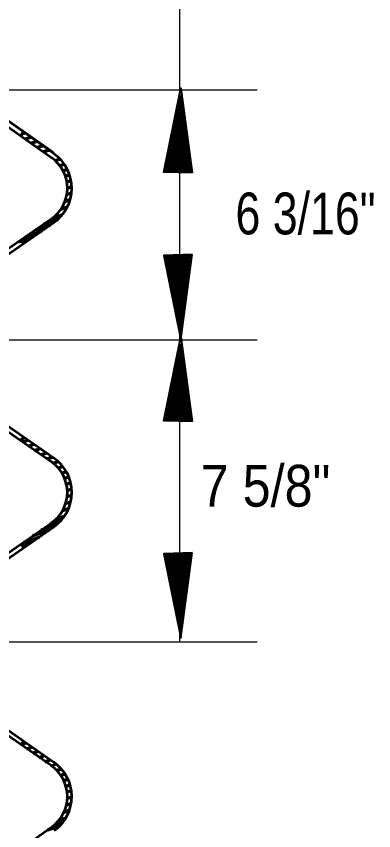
# Model space of a CAD drawing. Extents: x 856.9 to 891.7, y -2278.5 to -2254.7.
# Drawn here: x 865.843 to 866.943, y -2260.699 to -2258.193 of the extents above; entities that cross this region are included whole.
import ezdxf

# ---------------------------------------------------------------- set-up
doc = ezdxf.new("R2010")
doc.units = 0
doc.header["$LTSCALE"] = 0.051
doc.layers.add('1', color=7, linetype='Continuous', lineweight=70)
doc.layers.add('3', color=7, linetype='Continuous', lineweight=40)

msp = doc.modelspace()

# ---------------------------------------------------------------- hatches: boundary and pattern name
at = {"layer": '3'}
for points in [[(866.38433, -2258.675), (866.29767, -2258.67208), (866.34983, -2258.41367), (866.34983, -2258.41367)], [(866.38, -2258.67375), (866.302, -2258.671), (866.349, -2258.43842), (866.349, -2258.43842)], [(866.37608, -2258.6725), (866.306, -2258.67017), (866.34825, -2258.46083), (866.34825, -2258.46083)], [(866.37267, -2258.6715), (866.30958, -2258.66933), (866.34758, -2258.48083), (866.34758, -2258.48083)], [(866.36967, -2258.67058), (866.31283, -2258.66867), (866.347, -2258.49892), (866.347, -2258.49892)], [(866.36675, -2258.6695), (866.31567, -2258.66792), (866.3465, -2258.51517), (866.3465, -2258.51517)], [(866.36417, -2258.66883), (866.31825, -2258.66733), (866.346, -2258.52992), (866.346, -2258.52992)], [(866.362, -2258.668), (866.3205, -2258.66675), (866.3455, -2258.54317), (866.3455, -2258.54317)], [(866.36, -2258.66758), (866.32258, -2258.66625), (866.345, -2258.55492), (866.345, -2258.55492)], [(866.358, -2258.66683), (866.32433, -2258.66567), (866.34467, -2258.56575), (866.34467, -2258.56575)], [(866.3565, -2258.66642), (866.32617, -2258.66533), (866.34442, -2258.57533), (866.34442, -2258.57533)], [(866.35492, -2258.66592), (866.32775, -2258.66492), (866.344, -2258.58392), (866.344, -2258.58392)], [(866.35358, -2258.6655), (866.32908, -2258.66467), (866.34375, -2258.59183), (866.34375, -2258.59183)], [(866.35233, -2258.66492), (866.33025, -2258.66442), (866.34358, -2258.59875), (866.34358, -2258.59875)], [(866.35125, -2258.66475), (866.33142, -2258.66408), (866.34342, -2258.605), (866.34342, -2258.605)], [(866.35025, -2258.66433), (866.33242, -2258.66392), (866.34308, -2258.61067), (866.34308, -2258.61067)], [(866.34933, -2258.66417), (866.33325, -2258.66358), (866.34292, -2258.61575), (866.34292, -2258.61575)], [(866.3485, -2258.664), (866.33408, -2258.66342), (866.34275, -2258.62033), (866.34275, -2258.62033)], [(866.34808, -2258.66358), (866.33492, -2258.66333), (866.34275, -2258.62442), (866.34275, -2258.62442)], [(866.3475, -2258.66342), (866.33567, -2258.663), (866.34267, -2258.62808), (866.34267, -2258.62808)], [(866.347, -2258.66308), (866.33642, -2258.66267), (866.34283, -2258.63133), (866.34283, -2258.63133)], [(866.34642, -2258.66308), (866.337, -2258.66267), (866.34267, -2258.63442), (866.34267, -2258.63442)], [(866.34592, -2258.66292), (866.33742, -2258.66258), (866.34242, -2258.63717), (866.34242, -2258.63717)], [(866.3455, -2258.66267), (866.33792, -2258.6625), (866.3425, -2258.6395), (866.3425, -2258.6395)], [(866.38433, -2258.92583), (866.29767, -2258.92875), (866.34983, -2259.18717), (866.34983, -2259.18717)], [(866.38, -2258.92708), (866.302, -2258.92983), (866.349, -2259.16242), (866.349, -2259.16242)], [(866.37608, -2258.92833), (866.306, -2258.93067), (866.34825, -2259.14), (866.34825, -2259.14)], [(866.37267, -2258.92933), (866.30958, -2258.9315), (866.34758, -2259.12), (866.34758, -2259.12)], [(866.36967, -2258.93025), (866.31283, -2258.93217), (866.347, -2259.10192), (866.347, -2259.10192)], [(866.36675, -2258.93133), (866.31567, -2258.93292), (866.3465, -2259.08567), (866.3465, -2259.08567)], [(866.36417, -2258.932), (866.31825, -2258.9335), (866.346, -2259.07092), (866.346, -2259.07092)], [(866.362, -2258.93283), (866.3205, -2258.93408), (866.3455, -2259.05767), (866.3455, -2259.05767)], [(866.36, -2258.93325), (866.32258, -2258.93458), (866.345, -2259.04592), (866.345, -2259.04592)], [(866.358, -2258.934), (866.32433, -2258.93517), (866.34467, -2259.03508), (866.34467, -2259.03508)], [(866.3565, -2258.93442), (866.32617, -2258.9355), (866.34442, -2259.0255), (866.34442, -2259.0255)], [(866.35492, -2258.93492), (866.32775, -2258.93592), (866.344, -2259.01692), (866.344, -2259.01692)], [(866.35358, -2258.93533), (866.32908, -2258.93617), (866.34375, -2259.009), (866.34375, -2259.009)], [(866.35233, -2258.93592), (866.33025, -2258.93642), (866.34358, -2259.00208), (866.34358, -2259.00208)], [(866.35125, -2258.93608), (866.33142, -2258.93675), (866.34342, -2258.99583), (866.34342, -2258.99583)], [(866.35025, -2258.9365), (866.33242, -2258.93692), (866.34308, -2258.99017), (866.34308, -2258.99017)], [(866.34933, -2258.93667), (866.33325, -2258.93725), (866.34292, -2258.98508), (866.34292, -2258.98508)], [(866.3485, -2258.93683), (866.33408, -2258.93742), (866.34275, -2258.9805), (866.34275, -2258.9805)], [(866.34808, -2258.93725), (866.33492, -2258.9375), (866.34275, -2258.97642), (866.34275, -2258.97642)], [(866.3475, -2258.93742), (866.33567, -2258.93783), (866.34267, -2258.97275), (866.34267, -2258.97275)], [(866.347, -2258.93775), (866.33642, -2258.93817), (866.34283, -2258.9695), (866.34283, -2258.9695)], [(866.34642, -2258.93775), (866.337, -2258.93817), (866.34267, -2258.96642), (866.34267, -2258.96642)], [(866.34592, -2258.93792), (866.33742, -2258.93825), (866.34242, -2258.96367), (866.34242, -2258.96367)], [(866.3455, -2258.93817), (866.33792, -2258.93833), (866.3425, -2258.96133), (866.3425, -2258.96133)], [(866.38433, -2259.44017), (866.29767, -2259.43725), (866.34983, -2259.17883), (866.34983, -2259.17883)], [(866.38, -2259.43892), (866.302, -2259.43617), (866.349, -2259.20358), (866.349, -2259.20358)], [(866.37608, -2259.43767), (866.306, -2259.43533), (866.34825, -2259.226), (866.34825, -2259.226)], [(866.37267, -2259.43667), (866.30958, -2259.4345), (866.34758, -2259.246), (866.34758, -2259.246)], [(866.36967, -2259.43575), (866.31283, -2259.43383), (866.347, -2259.26408), (866.347, -2259.26408)], [(866.36675, -2259.43467), (866.31567, -2259.43308), (866.3465, -2259.28033), (866.3465, -2259.28033)], [(866.36417, -2259.434), (866.31825, -2259.4325), (866.346, -2259.29508), (866.346, -2259.29508)], [(866.362, -2259.43317), (866.3205, -2259.43192), (866.3455, -2259.30833), (866.3455, -2259.30833)], [(866.36, -2259.43275), (866.32258, -2259.43142), (866.345, -2259.32008), (866.345, -2259.32008)], [(866.358, -2259.432), (866.32433, -2259.43083), (866.34467, -2259.33092), (866.34467, -2259.33092)], [(866.3565, -2259.43158), (866.32617, -2259.4305), (866.34442, -2259.3405), (866.34442, -2259.3405)], [(866.35492, -2259.43108), (866.32775, -2259.43008), (866.344, -2259.34908), (866.344, -2259.34908)], [(866.35358, -2259.43067), (866.32908, -2259.42983), (866.34375, -2259.357), (866.34375, -2259.357)], [(866.35233, -2259.43008), (866.33025, -2259.42958), (866.34358, -2259.36392), (866.34358, -2259.36392)], [(866.35125, -2259.42992), (866.33142, -2259.42925), (866.34342, -2259.37017), (866.34342, -2259.37017)], [(866.35025, -2259.4295), (866.33242, -2259.42908), (866.34308, -2259.37583), (866.34308, -2259.37583)], [(866.34933, -2259.42933), (866.33325, -2259.42875), (866.34292, -2259.38092), (866.34292, -2259.38092)], [(866.3485, -2259.42917), (866.33408, -2259.42858), (866.34275, -2259.3855), (866.34275, -2259.3855)], [(866.34808, -2259.42875), (866.33492, -2259.4285), (866.34275, -2259.38958), (866.34275, -2259.38958)], [(866.3475, -2259.42858), (866.33567, -2259.42817), (866.34267, -2259.39325), (866.34267, -2259.39325)], [(866.347, -2259.42825), (866.33642, -2259.42783), (866.34283, -2259.3965), (866.34283, -2259.3965)], [(866.34642, -2259.42825), (866.337, -2259.42783), (866.34267, -2259.39958), (866.34267, -2259.39958)], [(866.34592, -2259.42808), (866.33742, -2259.42775), (866.34242, -2259.40233), (866.34242, -2259.40233)], [(866.3455, -2259.42783), (866.33792, -2259.42767), (866.3425, -2259.40467), (866.3425, -2259.40467)], [(866.38433, -2259.84417), (866.29767, -2259.84708), (866.34983, -2260.1055), (866.34983, -2260.1055)], [(866.38, -2259.84542), (866.302, -2259.84817), (866.349, -2260.08075), (866.349, -2260.08075)], [(866.37608, -2259.84667), (866.306, -2259.849), (866.34825, -2260.05833), (866.34825, -2260.05833)], [(866.37267, -2259.84767), (866.30958, -2259.84983), (866.34758, -2260.03833), (866.34758, -2260.03833)], [(866.36967, -2259.84858), (866.31283, -2259.8505), (866.347, -2260.02025), (866.347, -2260.02025)], [(866.36675, -2259.84967), (866.31567, -2259.85125), (866.3465, -2260.004), (866.3465, -2260.004)], [(866.36417, -2259.85033), (866.31825, -2259.85183), (866.346, -2259.98925), (866.346, -2259.98925)], [(866.362, -2259.85117), (866.3205, -2259.85242), (866.3455, -2259.976), (866.3455, -2259.976)], [(866.36, -2259.85158), (866.32258, -2259.85292), (866.345, -2259.96425), (866.345, -2259.96425)], [(866.358, -2259.85233), (866.32433, -2259.8535), (866.34467, -2259.95342), (866.34467, -2259.95342)], [(866.3565, -2259.85275), (866.32617, -2259.85383), (866.34442, -2259.94383), (866.34442, -2259.94383)], [(866.35492, -2259.85325), (866.32775, -2259.85425), (866.344, -2259.93525), (866.344, -2259.93525)], [(866.35358, -2259.85367), (866.32908, -2259.8545), (866.34375, -2259.92733), (866.34375, -2259.92733)], [(866.35233, -2259.85425), (866.33025, -2259.85475), (866.34358, -2259.92042), (866.34358, -2259.92042)], [(866.35125, -2259.85442), (866.33142, -2259.85508), (866.34342, -2259.91417), (866.34342, -2259.91417)], [(866.35025, -2259.85483), (866.33242, -2259.85525), (866.34308, -2259.9085), (866.34308, -2259.9085)], [(866.34933, -2259.855), (866.33325, -2259.85558), (866.34292, -2259.90342), (866.34292, -2259.90342)], [(866.3485, -2259.85517), (866.33408, -2259.85575), (866.34275, -2259.89883), (866.34275, -2259.89883)], [(866.34808, -2259.85558), (866.33492, -2259.85583), (866.34275, -2259.89475), (866.34275, -2259.89475)], [(866.3475, -2259.85575), (866.33567, -2259.85617), (866.34267, -2259.89108), (866.34267, -2259.89108)], [(866.347, -2259.85608), (866.33642, -2259.8565), (866.34283, -2259.88783), (866.34283, -2259.88783)], [(866.34642, -2259.85608), (866.337, -2259.8565), (866.34267, -2259.88475), (866.34267, -2259.88475)], [(866.34592, -2259.85625), (866.33742, -2259.85658), (866.34242, -2259.882), (866.34242, -2259.882)], [(866.3455, -2259.8565), (866.33792, -2259.85667), (866.3425, -2259.87967), (866.3425, -2259.87967)]]:
    msp.add_hatch(color=256, dxfattribs=at).paths.add_polyline_path(points)

# ---------------------------------------------------------------- linework, layer by layer
at = {"layer": '1', "lineweight": 25}
for p, q in [((866.347, -2260.11883), (866.347, -2257.74608)), ((866.58492, -2258.42008), (865.81925, -2258.42008)), ((866.58492, -2259.18958), (863.90775, -2259.18958)), ((866.58492, -2260.11883), (863.90775, -2260.11883))]:
    msp.add_line(p, q, dxfattribs=at)
at = {"layer": '1', "lineweight": 53}
for p, q in [((865.73217, -2258.47225), (865.95233, -2258.62867)), ((865.96092, -2258.61692), (865.74108, -2258.4605)), ((865.95633, -2258.61175), (865.74108, -2258.46092)), ((865.95067, -2258.81675), (865.66458, -2259.01475)), ((865.67217, -2259.0265), (865.95933, -2258.82742)), ((865.95933, -2259.5525), (865.67217, -2259.35342)), ((865.66458, -2259.3655), (865.95067, -2259.56317)), ((865.95067, -2259.75317), (865.66458, -2259.95042)), ((865.67217, -2259.96175), (865.95933, -2259.76342)), ((865.95067, -2260.49867), (865.66458, -2260.30117)), ((865.95933, -2260.48867), (865.67217, -2260.28917)), ((865.95067, -2260.49867), (865.96717, -2260.49417)), ((865.95233, -2260.68767), (865.73258, -2260.844))]:
    msp.add_line(p, q, dxfattribs=at)
at = {"layer": '1'}
for p, q in [((865.85767, -2258.56075), (865.86492, -2258.5505)), ((865.86367, -2258.5535), (865.86792, -2258.55217)), ((865.87092, -2258.56967), (865.88708, -2258.56525)), ((865.88858, -2258.58317), (865.90458, -2258.57842)), ((865.90792, -2258.596), (865.92417, -2258.59192)), ((865.92708, -2258.60917), (865.94317, -2258.60492)), ((865.96233, -2258.63725), (865.97708, -2258.6315)), ((865.97708, -2258.65192), (865.99017, -2258.64775)), ((865.98758, -2258.668), (866.00058, -2258.66375)), ((865.99467, -2258.6845), (866.00808, -2258.68)), ((865.99917, -2258.70217), (866.01258, -2258.69792)), ((866.00058, -2258.7215), (866.01383, -2258.71717)), ((865.99317, -2258.76275), (866.00933, -2258.75675)), ((865.99917, -2258.74067), (866.01383, -2258.73617)), ((865.98158, -2258.786), (866.00058, -2258.779)), ((865.95483, -2258.81425), (865.98442, -2258.804)), ((865.90342, -2258.84975), (865.94742, -2258.83517)), ((865.92858, -2258.83175), (865.97108, -2258.818)), ((865.87692, -2258.86892), (865.92108, -2258.854)), ((865.85033, -2258.8865), (865.89458, -2258.87167)), ((865.85767, -2258.88067), (865.86642, -2258.89225)), ((865.85767, -2259.49967), (865.86642, -2259.48767)), ((865.86217, -2259.50242), (865.87842, -2259.49667)), ((865.88133, -2259.51575), (865.89758, -2259.50975)), ((865.90017, -2259.529), (865.91658, -2259.52292)), ((865.91967, -2259.54092), (865.93608, -2259.53642)), ((865.93883, -2259.55375), (865.95492, -2259.5495)), ((865.95792, -2259.5675), (865.97258, -2259.56317)), ((865.97258, -2259.58217), (865.98592, -2259.57775)), ((865.98442, -2259.59825), (865.99767, -2259.59392)), ((865.99192, -2259.6145), (866.00508, -2259.61)), ((865.99767, -2259.63217), (866.01108, -2259.6275)), ((866.00058, -2259.6515), (866.01383, -2259.64717)), ((865.99642, -2259.691), (866.01108, -2259.6865)), ((865.99917, -2259.67042), (866.01383, -2259.66592)), ((865.98592, -2259.71342), (866.00358, -2259.70717)), ((865.96717, -2259.73942), (865.99192, -2259.731)), ((865.92108, -2259.7735), (865.96533, -2259.75892)), ((865.94742, -2259.75592), (865.98158, -2259.74417)), ((865.89458, -2259.791), (865.94058, -2259.77642)), ((865.86792, -2259.81067), (865.91392, -2259.79592)), ((865.85767, -2259.81625), (865.86642, -2259.82775)), ((865.86217, -2259.82217), (865.88708, -2259.81317)), ((865.85767, -2260.43525), (865.86642, -2260.42342)), ((865.86067, -2260.43225), (865.87242, -2260.42792)), ((865.87508, -2260.44692), (865.89142, -2260.44142)), ((865.89458, -2260.46042), (865.91067, -2260.45417)), ((865.91392, -2260.47367), (865.93008, -2260.4675)), ((865.93133, -2260.487), (865.94742, -2260.48075)), ((865.96833, -2260.513), (865.98158, -2260.50925)), ((865.97992, -2260.528), (865.99317, -2260.52375)), ((865.99017, -2260.54442), (866.00208, -2260.53967)), ((865.99642, -2260.562), (866.00933, -2260.5575)), ((865.99917, -2260.57967), (866.01258, -2260.57525)), ((866.00058, -2260.59892), (866.01383, -2260.59442)), ((865.99017, -2260.64167), (866.00658, -2260.63567)), ((865.99767, -2260.6195), (866.01258, -2260.615)), ((865.97542, -2260.66517), (865.99642, -2260.65925)), ((865.94058, -2260.696), (865.97708, -2260.68425)), ((865.96233, -2260.67992), (865.98867, -2260.67117))]:
    msp.add_line(p, q, dxfattribs=at)
at = {"layer": '1', "lineweight": 53}
for centre, radius, start, end in [((865.88544, -2258.72184), 0.11508, 304.74043, 54.50779), ((865.88544, -2258.72184), 0.12871, 304.74043, 54.5106), ((865.88544, -2259.65784), 0.12871, 304.74043, 55.25957), ((865.88544, -2259.65784), 0.11508, 304.73767, 55.26233), ((865.88544, -2260.59384), 0.12871, 305.4894, 55.25957), ((865.88544, -2260.59384), 0.11508, 305.49221, 55.25957)]:
    msp.add_arc(centre, radius, start, end, dxfattribs=at)
at = {"layer": '3'}
for points in [[(866.38433, -2258.675), (866.29767, -2258.67208), (866.34983, -2258.41367), (866.34983, -2258.41367)], [(866.38, -2258.67375), (866.302, -2258.671), (866.349, -2258.43842), (866.349, -2258.43842)], [(866.37608, -2258.6725), (866.306, -2258.67017), (866.34825, -2258.46083), (866.34825, -2258.46083)], [(866.37267, -2258.6715), (866.30958, -2258.66933), (866.34758, -2258.48083), (866.34758, -2258.48083)], [(866.36967, -2258.67058), (866.31283, -2258.66867), (866.347, -2258.49892), (866.347, -2258.49892)], [(866.36675, -2258.6695), (866.31567, -2258.66792), (866.3465, -2258.51517), (866.3465, -2258.51517)], [(866.36417, -2258.66883), (866.31825, -2258.66733), (866.346, -2258.52992), (866.346, -2258.52992)], [(866.362, -2258.668), (866.3205, -2258.66675), (866.3455, -2258.54317), (866.3455, -2258.54317)], [(866.36, -2258.66758), (866.32258, -2258.66625), (866.345, -2258.55492), (866.345, -2258.55492)], [(866.358, -2258.66683), (866.32433, -2258.66567), (866.34467, -2258.56575), (866.34467, -2258.56575)], [(866.3565, -2258.66642), (866.32617, -2258.66533), (866.34442, -2258.57533), (866.34442, -2258.57533)], [(866.35492, -2258.66592), (866.32775, -2258.66492), (866.344, -2258.58392), (866.344, -2258.58392)], [(866.35358, -2258.6655), (866.32908, -2258.66467), (866.34375, -2258.59183), (866.34375, -2258.59183)], [(866.35233, -2258.66492), (866.33025, -2258.66442), (866.34358, -2258.59875), (866.34358, -2258.59875)], [(866.35125, -2258.66475), (866.33142, -2258.66408), (866.34342, -2258.605), (866.34342, -2258.605)], [(866.35025, -2258.66433), (866.33242, -2258.66392), (866.34308, -2258.61067), (866.34308, -2258.61067)], [(866.34933, -2258.66417), (866.33325, -2258.66358), (866.34292, -2258.61575), (866.34292, -2258.61575)], [(866.3485, -2258.664), (866.33408, -2258.66342), (866.34275, -2258.62033), (866.34275, -2258.62033)], [(866.34808, -2258.66358), (866.33492, -2258.66333), (866.34275, -2258.62442), (866.34275, -2258.62442)], [(866.3475, -2258.66342), (866.33567, -2258.663), (866.34267, -2258.62808), (866.34267, -2258.62808)], [(866.347, -2258.66308), (866.33642, -2258.66267), (866.34283, -2258.63133), (866.34283, -2258.63133)], [(866.34642, -2258.66308), (866.337, -2258.66267), (866.34267, -2258.63442), (866.34267, -2258.63442)], [(866.34592, -2258.66292), (866.33742, -2258.66258), (866.34242, -2258.63717), (866.34242, -2258.63717)], [(866.3455, -2258.66267), (866.33792, -2258.6625), (866.3425, -2258.6395), (866.3425, -2258.6395)], [(866.38433, -2258.92583), (866.29767, -2258.92875), (866.34983, -2259.18717), (866.34983, -2259.18717)], [(866.38, -2258.92708), (866.302, -2258.92983), (866.349, -2259.16242), (866.349, -2259.16242)], [(866.37608, -2258.92833), (866.306, -2258.93067), (866.34825, -2259.14), (866.34825, -2259.14)], [(866.37267, -2258.92933), (866.30958, -2258.9315), (866.34758, -2259.12), (866.34758, -2259.12)], [(866.36967, -2258.93025), (866.31283, -2258.93217), (866.347, -2259.10192), (866.347, -2259.10192)], [(866.36675, -2258.93133), (866.31567, -2258.93292), (866.3465, -2259.08567), (866.3465, -2259.08567)], [(866.36417, -2258.932), (866.31825, -2258.9335), (866.346, -2259.07092), (866.346, -2259.07092)], [(866.362, -2258.93283), (866.3205, -2258.93408), (866.3455, -2259.05767), (866.3455, -2259.05767)], [(866.36, -2258.93325), (866.32258, -2258.93458), (866.345, -2259.04592), (866.345, -2259.04592)], [(866.358, -2258.934), (866.32433, -2258.93517), (866.34467, -2259.03508), (866.34467, -2259.03508)], [(866.3565, -2258.93442), (866.32617, -2258.9355), (866.34442, -2259.0255), (866.34442, -2259.0255)], [(866.35492, -2258.93492), (866.32775, -2258.93592), (866.344, -2259.01692), (866.344, -2259.01692)], [(866.35358, -2258.93533), (866.32908, -2258.93617), (866.34375, -2259.009), (866.34375, -2259.009)], [(866.35233, -2258.93592), (866.33025, -2258.93642), (866.34358, -2259.00208), (866.34358, -2259.00208)], [(866.35125, -2258.93608), (866.33142, -2258.93675), (866.34342, -2258.99583), (866.34342, -2258.99583)], [(866.35025, -2258.9365), (866.33242, -2258.93692), (866.34308, -2258.99017), (866.34308, -2258.99017)], [(866.34933, -2258.93667), (866.33325, -2258.93725), (866.34292, -2258.98508), (866.34292, -2258.98508)], [(866.3485, -2258.93683), (866.33408, -2258.93742), (866.34275, -2258.9805), (866.34275, -2258.9805)], [(866.34808, -2258.93725), (866.33492, -2258.9375), (866.34275, -2258.97642), (866.34275, -2258.97642)], [(866.3475, -2258.93742), (866.33567, -2258.93783), (866.34267, -2258.97275), (866.34267, -2258.97275)], [(866.347, -2258.93775), (866.33642, -2258.93817), (866.34283, -2258.9695), (866.34283, -2258.9695)], [(866.34642, -2258.93775), (866.337, -2258.93817), (866.34267, -2258.96642), (866.34267, -2258.96642)], [(866.34592, -2258.93792), (866.33742, -2258.93825), (866.34242, -2258.96367), (866.34242, -2258.96367)], [(866.3455, -2258.93817), (866.33792, -2258.93833), (866.3425, -2258.96133), (866.3425, -2258.96133)], [(866.38433, -2259.44017), (866.29767, -2259.43725), (866.34983, -2259.17883), (866.34983, -2259.17883)], [(866.38, -2259.43892), (866.302, -2259.43617), (866.349, -2259.20358), (866.349, -2259.20358)], [(866.37608, -2259.43767), (866.306, -2259.43533), (866.34825, -2259.226), (866.34825, -2259.226)], [(866.37267, -2259.43667), (866.30958, -2259.4345), (866.34758, -2259.246), (866.34758, -2259.246)], [(866.36967, -2259.43575), (866.31283, -2259.43383), (866.347, -2259.26408), (866.347, -2259.26408)], [(866.36675, -2259.43467), (866.31567, -2259.43308), (866.3465, -2259.28033), (866.3465, -2259.28033)], [(866.36417, -2259.434), (866.31825, -2259.4325), (866.346, -2259.29508), (866.346, -2259.29508)], [(866.362, -2259.43317), (866.3205, -2259.43192), (866.3455, -2259.30833), (866.3455, -2259.30833)], [(866.36, -2259.43275), (866.32258, -2259.43142), (866.345, -2259.32008), (866.345, -2259.32008)], [(866.358, -2259.432), (866.32433, -2259.43083), (866.34467, -2259.33092), (866.34467, -2259.33092)], [(866.3565, -2259.43158), (866.32617, -2259.4305), (866.34442, -2259.3405), (866.34442, -2259.3405)], [(866.35492, -2259.43108), (866.32775, -2259.43008), (866.344, -2259.34908), (866.344, -2259.34908)], [(866.35358, -2259.43067), (866.32908, -2259.42983), (866.34375, -2259.357), (866.34375, -2259.357)], [(866.35233, -2259.43008), (866.33025, -2259.42958), (866.34358, -2259.36392), (866.34358, -2259.36392)], [(866.35125, -2259.42992), (866.33142, -2259.42925), (866.34342, -2259.37017), (866.34342, -2259.37017)], [(866.35025, -2259.4295), (866.33242, -2259.42908), (866.34308, -2259.37583), (866.34308, -2259.37583)], [(866.34933, -2259.42933), (866.33325, -2259.42875), (866.34292, -2259.38092), (866.34292, -2259.38092)], [(866.3485, -2259.42917), (866.33408, -2259.42858), (866.34275, -2259.3855), (866.34275, -2259.3855)], [(866.34808, -2259.42875), (866.33492, -2259.4285), (866.34275, -2259.38958), (866.34275, -2259.38958)], [(866.3475, -2259.42858), (866.33567, -2259.42817), (866.34267, -2259.39325), (866.34267, -2259.39325)], [(866.347, -2259.42825), (866.33642, -2259.42783), (866.34283, -2259.3965), (866.34283, -2259.3965)], [(866.34642, -2259.42825), (866.337, -2259.42783), (866.34267, -2259.39958), (866.34267, -2259.39958)], [(866.34592, -2259.42808), (866.33742, -2259.42775), (866.34242, -2259.40233), (866.34242, -2259.40233)], [(866.3455, -2259.42783), (866.33792, -2259.42767), (866.3425, -2259.40467), (866.3425, -2259.40467)], [(866.38433, -2259.84417), (866.29767, -2259.84708), (866.34983, -2260.1055), (866.34983, -2260.1055)], [(866.38, -2259.84542), (866.302, -2259.84817), (866.349, -2260.08075), (866.349, -2260.08075)], [(866.37608, -2259.84667), (866.306, -2259.849), (866.34825, -2260.05833), (866.34825, -2260.05833)], [(866.37267, -2259.84767), (866.30958, -2259.84983), (866.34758, -2260.03833), (866.34758, -2260.03833)], [(866.36967, -2259.84858), (866.31283, -2259.8505), (866.347, -2260.02025), (866.347, -2260.02025)], [(866.36675, -2259.84967), (866.31567, -2259.85125), (866.3465, -2260.004), (866.3465, -2260.004)], [(866.36417, -2259.85033), (866.31825, -2259.85183), (866.346, -2259.98925), (866.346, -2259.98925)], [(866.362, -2259.85117), (866.3205, -2259.85242), (866.3455, -2259.976), (866.3455, -2259.976)], [(866.36, -2259.85158), (866.32258, -2259.85292), (866.345, -2259.96425), (866.345, -2259.96425)], [(866.358, -2259.85233), (866.32433, -2259.8535), (866.34467, -2259.95342), (866.34467, -2259.95342)], [(866.3565, -2259.85275), (866.32617, -2259.85383), (866.34442, -2259.94383), (866.34442, -2259.94383)], [(866.35492, -2259.85325), (866.32775, -2259.85425), (866.344, -2259.93525), (866.344, -2259.93525)], [(866.35358, -2259.85367), (866.32908, -2259.8545), (866.34375, -2259.92733), (866.34375, -2259.92733)], [(866.35233, -2259.85425), (866.33025, -2259.85475), (866.34358, -2259.92042), (866.34358, -2259.92042)], [(866.35125, -2259.85442), (866.33142, -2259.85508), (866.34342, -2259.91417), (866.34342, -2259.91417)], [(866.35025, -2259.85483), (866.33242, -2259.85525), (866.34308, -2259.9085), (866.34308, -2259.9085)], [(866.34933, -2259.855), (866.33325, -2259.85558), (866.34292, -2259.90342), (866.34292, -2259.90342)], [(866.3485, -2259.85517), (866.33408, -2259.85575), (866.34275, -2259.89883), (866.34275, -2259.89883)], [(866.34808, -2259.85558), (866.33492, -2259.85583), (866.34275, -2259.89475), (866.34275, -2259.89475)], [(866.3475, -2259.85575), (866.33567, -2259.85617), (866.34267, -2259.89108), (866.34267, -2259.89108)], [(866.347, -2259.85608), (866.33642, -2259.8565), (866.34283, -2259.88783), (866.34283, -2259.88783)], [(866.34642, -2259.85608), (866.337, -2259.8565), (866.34267, -2259.88475), (866.34267, -2259.88475)], [(866.34592, -2259.85625), (866.33742, -2259.85658), (866.34242, -2259.882), (866.34242, -2259.882)], [(866.3455, -2259.8565), (866.33792, -2259.85667), (866.3425, -2259.87967), (866.3425, -2259.87967)]]:
    msp.add_lwpolyline(points, close=True, dxfattribs=at)

# ---------------------------------------------------------------- texts
at = {"layer": '1'}
for s, width, p in [('6 3/16"', 0.8, (866.518, -2258.864)), ('7 5/8"', 0.9, (866.411, -2259.70167))]:
    msp.add_text(s, height=0.1286, dxfattribs=dict(at, width=width)).set_placement(p)

doc.saveas('drawing.dxf')
